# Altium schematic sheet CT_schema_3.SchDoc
size 405 x 311 mm
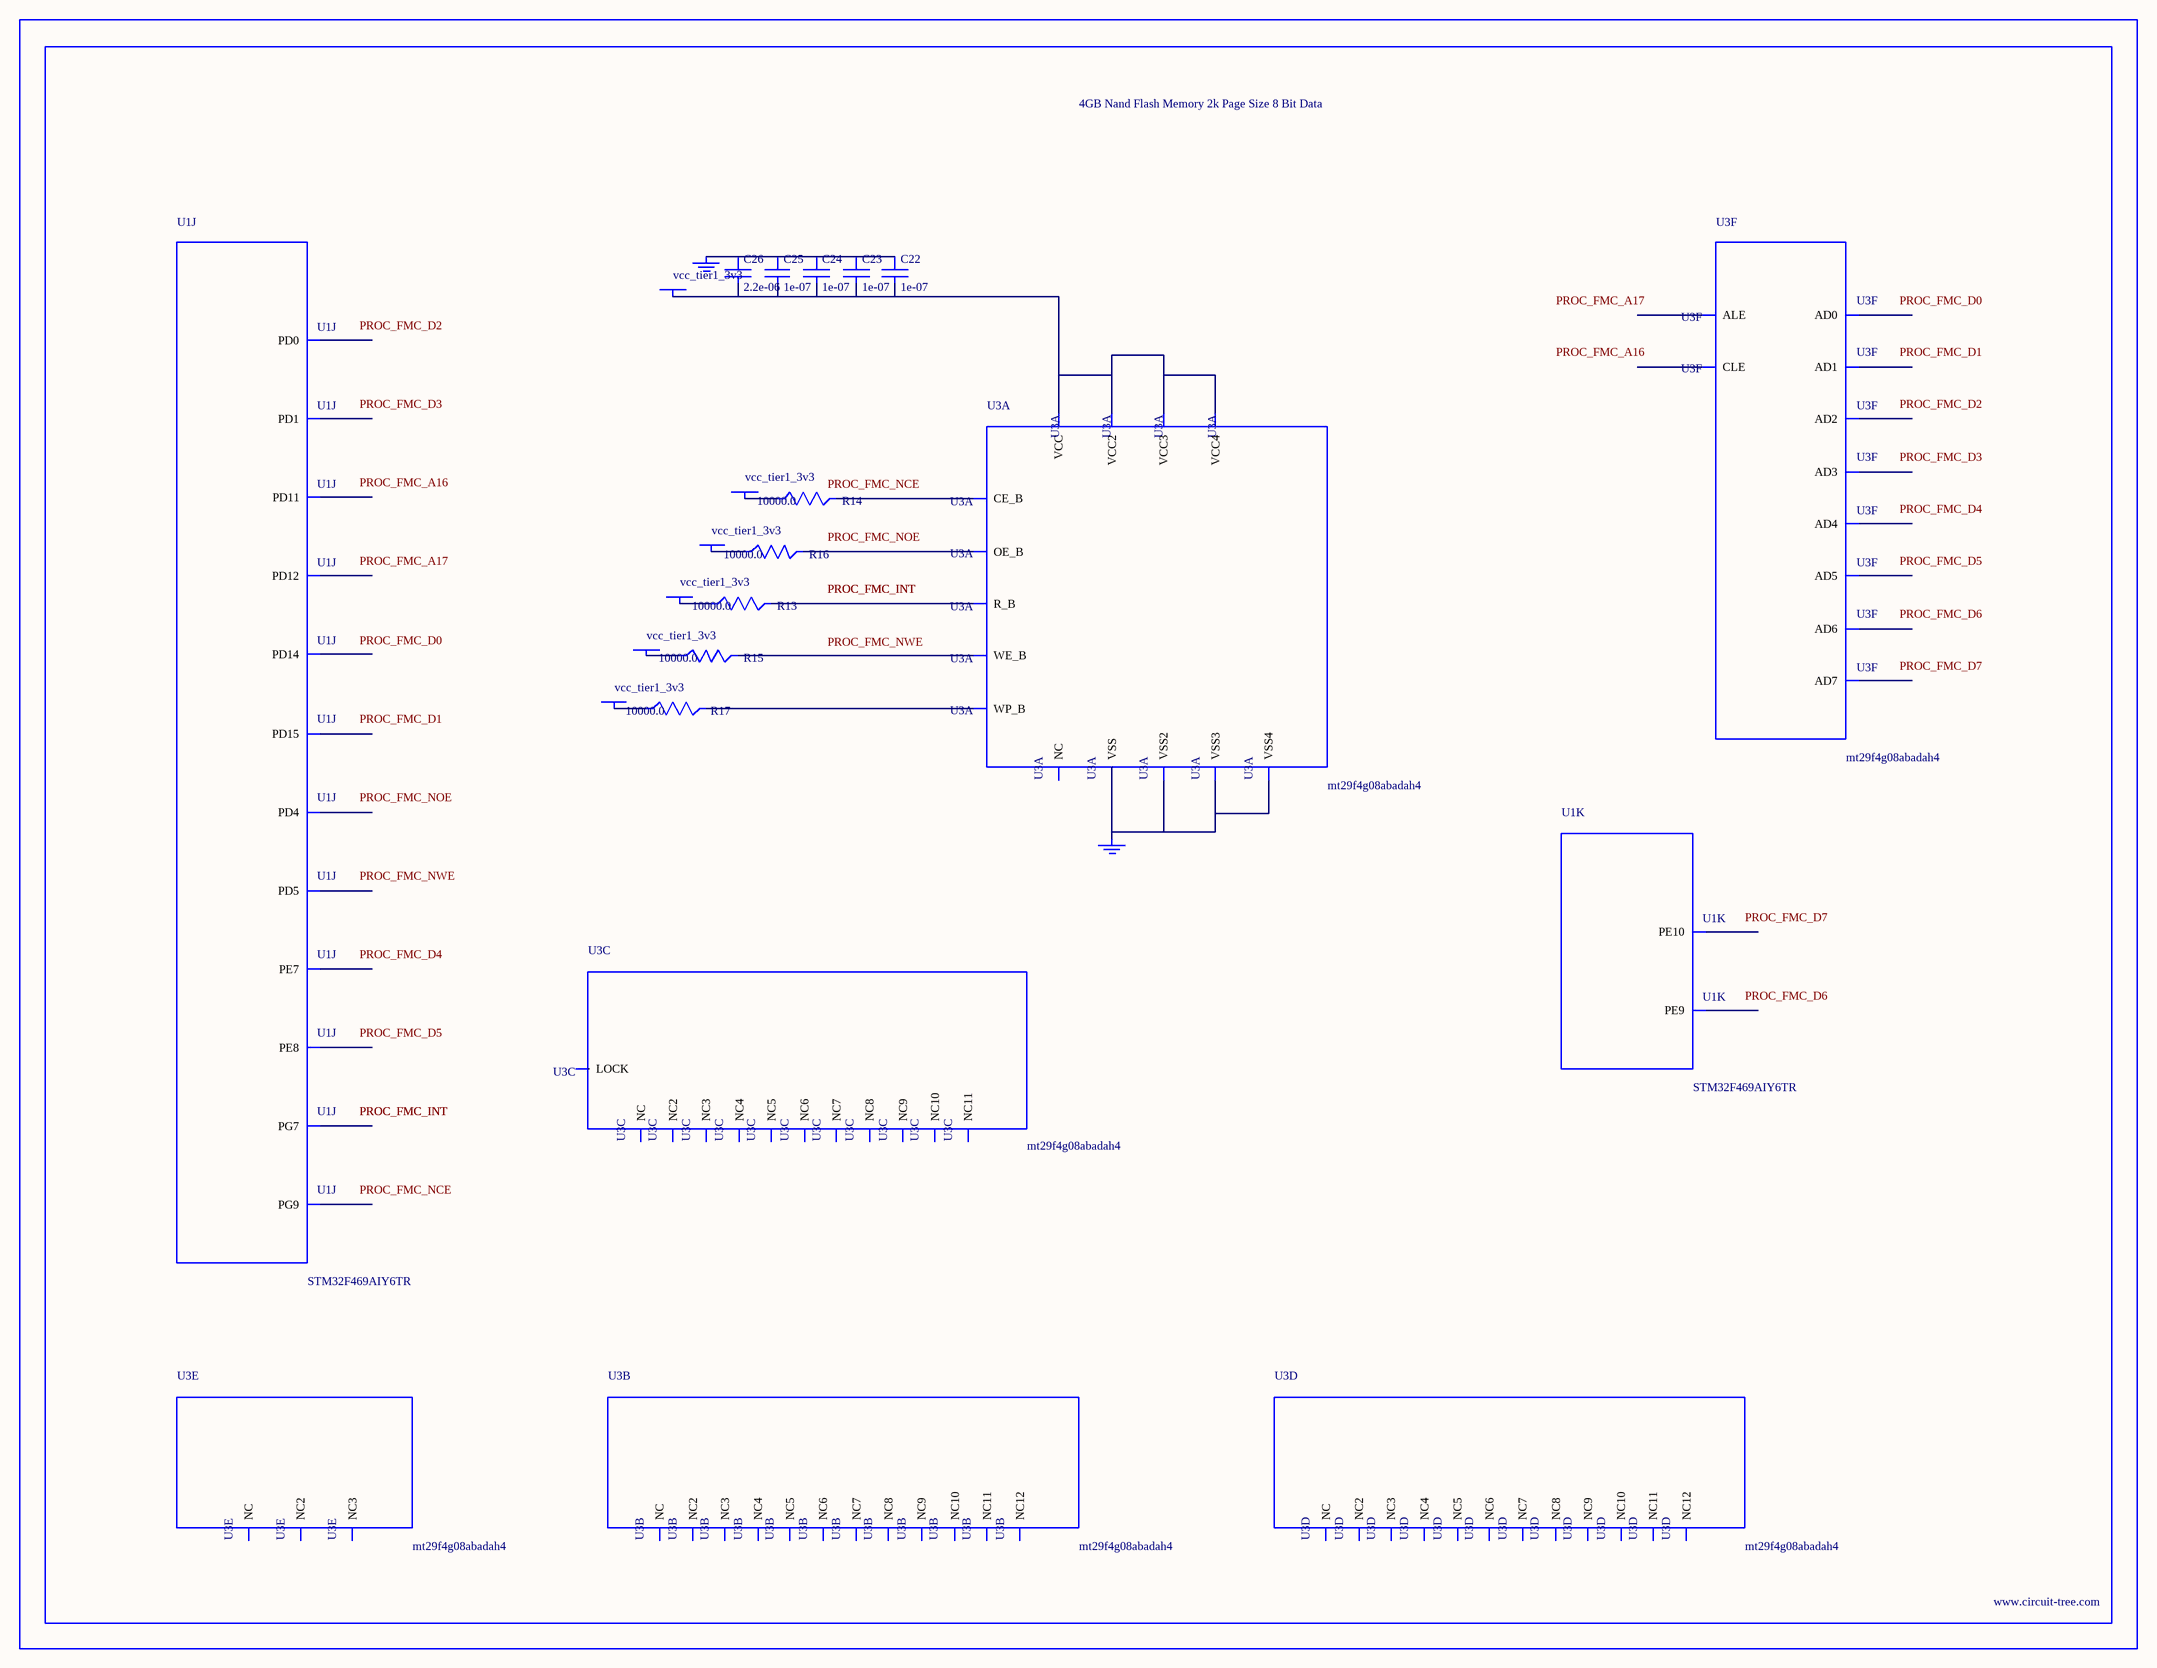
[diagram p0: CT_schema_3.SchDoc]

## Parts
BORDER2  (no value)
C22  1e-07  [C0402]
C23  1e-07  [C0402]
C24  1e-07  [C0402]
C25  1e-07  [C0402]
C26  2.2e-06  [C0603]
GND_INSTANCE_2_0  (no value)
GND_INSTANCE_2_1  (no value)
POWER_INSTANCE_2_0  vcc_tier1_3v3
POWER_INSTANCE_2_1  vcc_tier1_3v3
POWER_INSTANCE_2_2  vcc_tier1_3v3
POWER_INSTANCE_2_3  vcc_tier1_3v3
POWER_INSTANCE_2_4  vcc_tier1_3v3
POWER_INSTANCE_2_5  vcc_tier1_3v3
R13  10000.0  [R0603]
R14  10000.0  [R0603]
R15  10000.0  [R0603]
R16  10000.0  [R0603]
R17  10000.0  [R0603]
U1  STM32F469AIY6TR  [WLCSP168]  (parts J,K of 14)
U3  mt29f4g08abadah4  [VFBGA-63]  (parts A,B,C,D,E,F of 6)

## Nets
NetC22_1: C22.1 C23.1 C24.1 C25.1 C26.1 GND_INSTANCE_2_0.0(GND)
NetC22_2: C22.2 C23.2 C24.2 C25.2 C26.2 POWER_INSTANCE_2_0.0(PWR) U3.D3(VCC) U3.G4(VCC2) U3.H8(VCC3) U3.J6(VCC4)
NetGND_INSTANCE_2_1_0: GND_INSTANCE_2_1.0(GND) U3.C5(VSS) U3.F7(VSS2) U3.K3(VSS3) U3.K8(VSS4)
NetPOWER_INSTANCE_2_1_0: POWER_INSTANCE_2_1.0(PWR) R13.1
NetPOWER_INSTANCE_2_2_0: POWER_INSTANCE_2_2.0(PWR) R14.1
NetPOWER_INSTANCE_2_3_0: POWER_INSTANCE_2_3.0(PWR) R15.1
NetPOWER_INSTANCE_2_4_0: POWER_INSTANCE_2_4.0(PWR) R16.1
NetPOWER_INSTANCE_2_5_0: POWER_INSTANCE_2_5.0(PWR) R17.1
NetR13_2: R13.2 U3.C8(R_B)
NetR14_2: R14.2 U3.C6(CE_B)
NetR15_2: R15.2 U3.C7(WE_B)
NetR16_2: R16.2 U3.D4(OE_B)
NetR17_2: R17.2 U3.C3(WP_B)

Not connected (* = marked no-connect by the designer): U1 A3(PD1) B4(PD4) C6(PD5) D7(PG9) E6(PD0) H6(PG7) J4(PD11) K6(PE9) L2(PD15) L3(PD14) M2(PD12) M7(PE8) N7(PE7) P6(PE10); U3 A1(NC) A2(NC3) A9(NC4) A10(NC2) B1(NC5) B9(NC7) B10(NC6) C4(ALE) D5(CLE) D6(NC8) D7(NC9) D8(NC10) E3(NC11) E4(NC12) E5(NC) E6(NC2) E7(NC3) E8(NC4) F3(NC5) F4(NC6) F5(NC7) F6(NC8) F8(NC9) G3(NC) G5(LOCK) G6(NC10) G7(NC11) G8(NC) H3(NC2) H4(AD0) H5(NC3) H6(NC4) H7(NC5) J3(NC6) J4(AD1) J5(NC7) J7(AD5) J8(AD7) K4(AD2) K5(AD3) K6(AD4) K7(AD6) L1(NC8) L2(NC10) L9(NC11) L10(NC9) M1(NC12) M2(NC2) M9(NC3) M10(NC)

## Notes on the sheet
- Labels drawn without touching a wire or pin: PROC_FMC_A16, PROC_FMC_A17, PROC_FMC_D0, PROC_FMC_D1, PROC_FMC_D2, PROC_FMC_D3, PROC_FMC_D4, PROC_FMC_D5, PROC_FMC_D6, PROC_FMC_D7, PROC_FMC_NCE, PROC_FMC_NOE, PROC_FMC_NWE

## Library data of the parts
BORDER2 = BORDER_PAGE2
C22-C25 = C0402C104K3RACTU
C26 = C0603C225K8RACTU
GND_INSTANCE_2_0 GND_INSTANCE_2_1 = GND
POWER_INSTANCE_2_0-POWER_INSTANCE_2_5 = PWR
R13-R17 = RC0603JR-0710KL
